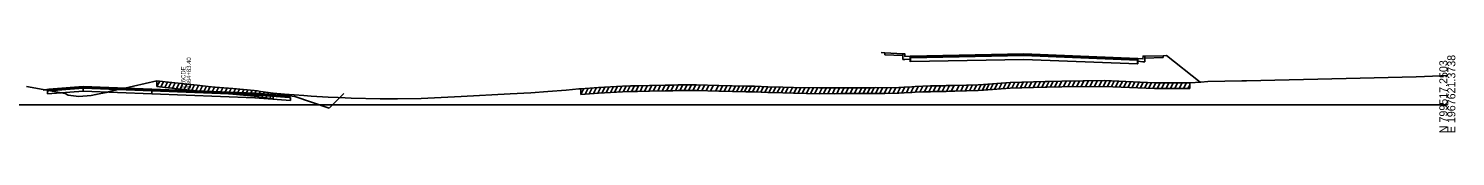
# Model space of a CAD drawing. Extents: x 1017 to 19997, y -1947 to 50737.
# Drawn here: x 14703.7 to 15202.8, y 14490.3 to 14518.2 of the extents above; entities that cross this region are included whole.
import ezdxf

# ---------------------------------------------------------------- set-up
doc = ezdxf.new("R2010")
doc.units = 0
for name, color, linetype in [('RD_GPK_XS_Cell', 7, 'Continuous'), ('RD_XS_Base', 7, 'Continuous'), ('RD_XS_CurbBase', 7, 'Continuous'), ('RD_XS_ExGround', 7, 'Continuous'), ('RD_XS_ExPaveRet', 7, 'Continuous'), ('RD_XS_Greenside', 7, 'Continuous'), ('RD_XS_Pave', 7, 'Continuous'), ('RD_XS_PaveOvlay', 7, 'Continuous'), ('RD_XS_SW', 7, 'Continuous'), ('RD_XS_SWbase', 7, 'Continuous'), ('RD_XS_TieSlope', 7, 'Continuous'), ('RD_XS_TX_Notes', 7, 'Continuous')]:
    doc.layers.add(name, color=color, linetype=linetype)

msp = doc.modelspace()

# ---------------------------------------------------------------- linework, layer by layer
at = {"layer": 'RD_GPK_XS_Cell'}
msp.add_line((14600, 14500), (15200, 14500), dxfattribs=at)
at = {"layer": 'RD_XS_Base'}
for points in [[(15012.08, 14515.09), (15012.08, 14516.43)], [(15012.21, 14515.1), (15012.08, 14515.09)], [(15012.21, 14515.1), (15012.21, 14516.43)], [(15091.58, 14514.29), (15051.89, 14515.9), (15012.21, 14515.1)], [(15091.58, 14515.62), (15091.58, 14514.29)], [(15091.7, 14515.62), (15091.7, 14514.28)], [(15091.7, 14514.28), (15091.58, 14514.29)], [(14710.32, 14504.78), (14710.82, 14504.82), (14722.82, 14505.79)], [(14722.82, 14504.79), (14710.32, 14503.78)], [(14710.32, 14503.78), (14710.32, 14504.78)], [(14722.82, 14504.79), (14722.82, 14505.79)], [(14782.83, 14502.46), (14758.82, 14503.39), (14722.82, 14504.79)], [(14746.82, 14504.86), (14746.82, 14503.86)], [(14782.83, 14502.46), (14758.82, 14503.39), (14746.82, 14503.86)], [(14782.83, 14503.46), (14782.83, 14502.46)], [(14782.83, 14503.46), (14794.83, 14502.51), (14795.33, 14502.47)], [(14795.33, 14501.47), (14782.83, 14502.46)], [(14795.33, 14502.47), (14795.33, 14501.47)]]:
    msp.add_lwpolyline(points, dxfattribs=at)
at = {"layer": 'RD_XS_CurbBase'}
for points in [[(15012.08, 14517.02), (15010.29, 14516.88), (15010.18, 14517.88), (15009.55, 14517.89)], [(15009.55, 14517.89), (15009.55, 14515.89)], [(15009.55, 14515.89), (15010.29, 14515.88), (15012.08, 14516.02)], [(15012.08, 14516.02), (15012.08, 14517.02)], [(15091.7, 14516.21), (15093.5, 14516.03), (15093.6, 14517.03), (15094.23, 14517.02)], [(15091.7, 14515.21), (15091.7, 14516.21)], [(15094.23, 14515.02), (15093.5, 14515.03), (15091.7, 14515.21)], [(15094.23, 14517.02), (15094.23, 14515.02)]]:
    msp.add_lwpolyline(points, dxfattribs=at)
at = {"layer": 'RD_XS_ExGround'}
msp.add_lwpolyline([(14702.99, 14506.37), (14716.51, 14503.89), (14717.58, 14503.31), (14721.28, 14502.85), (14725.61, 14503.19), (14727.28, 14503.52), (14730.93, 14504.25), (14733.02, 14504.83), (14736.32, 14505.58), (14748.65, 14508.33), (14751.54, 14508.01), (14757.26, 14507.44), (14759.06, 14507.25), (14762.67, 14506.84), (14766.55, 14506.41), (14769, 14506.15), (14775.14, 14505.66), (14782.63, 14504.99), (14783.78, 14504.82), (14784.9, 14504.64), (14789.27, 14504.03), (14791.96, 14503.77), (14793.25, 14503.68), (14799.96, 14503.17), (14802.54, 14503), (14808.56, 14502.68), (14812.03, 14502.48), (14814.53, 14502.36), (14816.53, 14502.28), (14826.74, 14502.05), (14827.29, 14502.04), (14828.39, 14502.01), (14832.79, 14502.1), (14841.06, 14502.14), (14855.03, 14502.88), (14872.19, 14503.85), (14879.41, 14504.11), (14885.37, 14504.63), (14891.81, 14505.08), (14896.21, 14505.51), (14896.9, 14505.57), (14903.03, 14506.09), (14911.54, 14506.51), (14914.28, 14506.58), (14916.75, 14506.65), (14920.96, 14506.73), (14926.42, 14506.84), (14929.03, 14506.89), (14930.94, 14506.95), (14936.11, 14506.95), (14936.93, 14506.95), (14937.41, 14506.96), (14945.2, 14506.77), (14954.6, 14506.54), (14957.66, 14506.47), (14962.29, 14506.31), (14967.62, 14506.17), (14971.27, 14506.07), (14980.41, 14505.86), (14981.09, 14505.88), (14985.75, 14505.86), (14988.27, 14505.87), (14988.91, 14505.87), (14990.77, 14505.89), (14993.05, 14505.9), (14998.86, 14505.94), (14999.91, 14505.98), (15003.19, 14505.94), (15008.16, 14506.08), (15009.95, 14506.14), (15012.73, 14506.31), (15013.84, 14506.36), (15016.53, 14506.49), (15019.24, 14506.57), (15020.34, 14506.61), (15023.13, 14506.65), (15024.15, 14506.67), (15024.64, 14506.68), (15025.78, 14506.71), (15026.81, 14506.73), (15027.68, 14506.74), (15035.9, 14506.97), (15037.7, 14507.09), (15047.11, 14507.81), (15059.38, 14508.13), (15059.96, 14508.18), (15065.13, 14508.29), (15080.09, 14508.43), (15097.55, 14507.71), (15109.88, 14507.63), (15113.72, 14507.86), (15116.17, 14508.08), (15128.17, 14508.4), (15128.72, 14508.41), (15129.69, 14508.41), (15164.57, 14509.15), (15189.07, 14509.81), (15197.69, 14510.13), (15200, 14510.19)], dxfattribs=at)
at = {"layer": 'RD_XS_ExPaveRet'}
for p, q in [((14748.65, 14506.33), (14748.65, 14508.33)), ((14748.65, 14506.33), (14749.6, 14508.23)), ((14750, 14506.18), (14750.95, 14508.08)), ((14751.35, 14506.04), (14752.3, 14507.94)), ((14752.71, 14505.9), (14753.66, 14507.8)), ((14754.06, 14505.76), (14755.02, 14507.66)), ((14755.42, 14505.62), (14756.37, 14507.53)), ((14756.78, 14505.48), (14757.73, 14507.39)), ((14758.15, 14505.35), (14759.11, 14507.25)), ((14759.52, 14505.2), (14760.47, 14507.09)), ((14760.89, 14505.04), (14761.83, 14506.94)), ((14762.25, 14504.89), (14763.2, 14506.78)), ((14763.62, 14504.73), (14764.56, 14506.63)), ((14764.98, 14504.58), (14765.93, 14506.48)), ((14766.35, 14504.43), (14767.3, 14506.33)), ((14767.79, 14504.28), (14768.74, 14506.17)), ((14769.25, 14504.13), (14770.21, 14506.05)), ((14770.72, 14504.01), (14771.68, 14505.93)), ((14772.19, 14503.89), (14773.15, 14505.82)), ((14773.66, 14503.78), (14774.62, 14505.7)), ((14775.13, 14503.66), (14776.08, 14505.58)), ((14776.59, 14503.53), (14777.55, 14505.45)), ((14778.05, 14503.4), (14779.01, 14505.31)), ((14779.52, 14503.27), (14780.47, 14505.18)), ((14780.98, 14503.14), (14781.94, 14505.05)), ((14782.44, 14503.01), (14783.38, 14504.88)), ((14783.87, 14502.81), (14784.79, 14504.66)), ((14785.29, 14502.59), (14786.22, 14504.46)), ((14896.9, 14503.57), (14897.95, 14505.66)), ((14896.9, 14503.57), (14896.9, 14505.57)), ((14898.39, 14503.69), (14899.43, 14505.78)), ((14899.88, 14503.82), (14900.92, 14505.91)), ((14901.37, 14503.95), (14902.41, 14506.03)), ((14902.86, 14504.07), (14903.88, 14506.13)), ((14904.32, 14504.15), (14905.34, 14506.2)), ((14905.79, 14504.22), (14906.81, 14506.28)), ((14907.27, 14504.3), (14908.29, 14506.35)), ((14908.74, 14504.37), (14909.77, 14506.42)), ((14910.22, 14504.45), (14911.25, 14506.5)), ((14911.7, 14504.52), (14912.71, 14506.54)), ((14913.16, 14504.55), (14914.17, 14506.58)), ((14914.62, 14504.59), (14915.64, 14506.62)), ((14916.09, 14504.63), (14917.1, 14506.66)), ((14917.62, 14504.67), (14918.63, 14506.68)), ((14919.16, 14504.69), (14920.17, 14506.71)), ((14920.71, 14504.72), (14921.72, 14506.74)), ((14922.25, 14504.76), (14923.26, 14506.78)), ((14923.8, 14504.79), (14924.81, 14506.81)), ((14925.34, 14504.82), (14926.35, 14506.84)), ((14926.88, 14504.85), (14927.89, 14506.87)), ((14928.43, 14504.88), (14929.44, 14506.9)), ((14929.98, 14504.92), (14931, 14506.95)), ((14931.53, 14504.95), (14932.53, 14506.95)), ((14933.07, 14504.95), (14934.07, 14506.95)), ((14934.6, 14504.95), (14935.6, 14506.95)), ((14936.14, 14504.95), (14937.14, 14506.95)), ((14937.67, 14504.95), (14938.66, 14506.93)), ((14939.19, 14504.91), (14940.18, 14506.89)), ((14940.71, 14504.88), (14941.69, 14506.85)), ((14942.29, 14504.84), (14943.27, 14506.82)), ((14944.03, 14504.8), (14945.02, 14506.77)), ((14945.56, 14504.76), (14946.54, 14506.74)), ((14947.08, 14504.72), (14948.07, 14506.7)), ((14948.55, 14504.69), (14949.54, 14506.66)), ((14950.02, 14504.65), (14951.01, 14506.63)), ((14951.46, 14504.62), (14952.45, 14506.59)), ((14952.88, 14504.58), (14953.87, 14506.56)), ((14954.13, 14504.55), (14955.12, 14506.53)), ((14955.52, 14504.52), (14956.51, 14506.5)), ((14956.97, 14504.48), (14957.95, 14506.46)), ((14958.4, 14504.44), (14959.39, 14506.41)), ((14959.84, 14504.39), (14960.82, 14506.36)), ((14961.28, 14504.35), (14962.26, 14506.31)), ((14962.71, 14504.3), (14963.7, 14506.27)), ((14964.15, 14504.26), (14965.14, 14506.23)), ((14965.59, 14504.22), (14966.58, 14506.2)), ((14967.03, 14504.18), (14968.01, 14506.16)), ((14968.49, 14504.14), (14969.48, 14506.12)), ((14969.96, 14504.11), (14970.94, 14506.08)), ((14971.42, 14504.07), (14972.41, 14506.05)), ((14972.89, 14504.04), (14973.88, 14506.01)), ((14974.36, 14504), (14975.34, 14505.98)), ((14975.82, 14503.97), (14976.81, 14505.94)), ((14977.29, 14503.93), (14978.28, 14505.91)), ((14978.76, 14503.9), (14979.74, 14505.87)), ((14980.27, 14503.86), (14981.29, 14505.88)), ((14981.82, 14503.88), (14982.82, 14505.87)), ((14983.36, 14503.87), (14984.36, 14505.87)), ((14984.89, 14503.86), (14985.89, 14505.86)), ((14986.43, 14503.86), (14987.43, 14505.87)), ((14987.97, 14503.87), (14988.98, 14505.88)), ((14989.52, 14503.88), (14990.52, 14505.89)), ((14991.06, 14503.89), (14992.06, 14505.9)), ((14992.61, 14503.9), (14993.62, 14505.9)), ((14994.17, 14503.91), (14995.18, 14505.92)), ((14995.62, 14503.92), (14996.63, 14505.93)), ((14997.07, 14503.93), (14998.07, 14505.94)), ((14998.52, 14503.94), (14999.53, 14505.96)), ((14999.98, 14503.98), (15000.97, 14505.96)), ((15001.49, 14503.96), (15002.48, 14505.95)), ((15003.01, 14503.94), (15004.02, 14505.96)), ((15004.55, 14503.98), (15005.57, 14506.01)), ((15006.1, 14504.02), (15007.12, 14506.05)), ((15007.66, 14504.07), (15008.67, 14506.1)), ((15009.21, 14504.12), (15010.23, 14506.16)), ((15010.78, 14504.19), (15011.81, 14506.26)), ((15012.35, 14504.29), (15013.38, 14506.34)), ((15013.93, 14504.37), (15014.95, 14506.41)), ((15015.5, 14504.44), (15016.52, 14506.49)), ((15017.07, 14504.5), (15018.08, 14506.53)), ((15018.63, 14504.55), (15019.64, 14506.58)), ((15020.19, 14504.6), (15021.2, 14506.62)), ((15021.74, 14504.63), (15022.74, 14506.65)), ((15023.28, 14504.66), (15024.29, 14506.68)), ((15024.83, 14504.68), (15025.84, 14506.71)), ((15026.45, 14504.72), (15027.46, 14506.74)), ((15028.24, 14504.76), (15029.25, 14506.79)), ((15029.8, 14504.8), (15030.81, 14506.83)), ((15031.36, 14504.85), (15032.38, 14506.88)), ((15032.88, 14504.89), (15033.89, 14506.92)), ((15034.38, 14504.93), (15035.4, 14506.96)), ((15035.86, 14504.97), (15036.89, 14507.04)), ((15037.35, 14505.06), (15038.38, 14507.14)), ((15038.65, 14505.16), (15039.69, 14507.24)), ((15040.12, 14505.27), (15041.16, 14507.35)), ((15041.64, 14505.39), (15042.68, 14507.47)), ((15043.16, 14505.5), (15044.19, 14507.58)), ((15044.67, 14505.62), (15045.71, 14507.7)), ((15046.19, 14505.74), (15047.23, 14507.81)), ((15047.69, 14505.82), (15048.71, 14507.85)), ((15049.17, 14505.86), (15050.18, 14507.89)), ((15050.65, 14505.9), (15051.66, 14507.93)), ((15052.13, 14505.94), (15053.14, 14507.97)), ((15053.63, 14505.98), (15054.64, 14508.01)), ((15055.13, 14506.02), (15056.15, 14508.04)), ((15056.64, 14506.06), (15057.65, 14508.08)), ((15058.14, 14506.1), (15059.15, 14508.12)), ((15059.65, 14506.15), (15060.68, 14508.2)), ((15061.16, 14506.21), (15062.18, 14508.23)), ((15062.66, 14506.24), (15063.68, 14508.26)), ((15064.16, 14506.27), (15065.17, 14508.29)), ((15065.71, 14506.3), (15066.72, 14508.31)), ((15067.26, 14506.31), (15068.26, 14508.32)), ((15068.81, 14506.33), (15069.81, 14508.34)), ((15070.35, 14506.34), (15071.36, 14508.35)), ((15071.9, 14506.36), (15072.9, 14508.37)), ((15073.44, 14506.37), (15074.45, 14508.38)), ((15074.99, 14506.39), (15076, 14508.39)), ((15076.54, 14506.4), (15077.54, 14508.41)), ((15078.09, 14506.41), (15079.1, 14508.42)), ((15079.66, 14506.43), (15080.65, 14508.41)), ((15081.1, 14506.39), (15082.08, 14508.35)), ((15082.52, 14506.33), (15083.5, 14508.29)), ((15083.95, 14506.27), (15084.93, 14508.23)), ((15085.38, 14506.21), (15086.36, 14508.17)), ((15086.83, 14506.15), (15087.81, 14508.11)), ((15088.29, 14506.09), (15089.27, 14508.05)), ((15089.74, 14506.03), (15090.72, 14507.99)), ((15091.2, 14505.97), (15092.18, 14507.93)), ((15092.65, 14505.91), (15093.63, 14507.87)), ((15094.1, 14505.85), (15095.08, 14507.81)), ((15095.56, 14505.79), (15096.54, 14507.75)), ((15097.01, 14505.73), (15098, 14507.7)), ((15098.53, 14505.7), (15099.53, 14507.69)), ((15100.07, 14505.69), (15101.06, 14507.69)), ((15101.6, 14505.68), (15102.6, 14507.68)), ((15103.14, 14505.67), (15104.13, 14507.67)), ((15104.67, 14505.66), (15105.67, 14507.66)), ((15106.2, 14505.65), (15107.2, 14507.65)), ((15107.74, 14505.64), (15108.73, 14507.64)), ((15109.27, 14505.64), (15109.88, 14506.85)), ((15109.88, 14505.63), (15109.88, 14507.63)), ((14786.72, 14502.39), (14787.65, 14504.26)), ((14788.15, 14502.19), (14789.08, 14504.06)), ((14789.27, 14502.03), (14789.27, 14504.03))]:
    msp.add_line(p, q, dxfattribs=at)
for points in [[(14748.65, 14506.33), (14751.54, 14506.01), (14757.26, 14505.44), (14759.06, 14505.25), (14762.67, 14504.84), (14766.55, 14504.41), (14769, 14504.15), (14775.14, 14503.66), (14782.63, 14502.99), (14783.78, 14502.82), (14784.9, 14502.64), (14789.27, 14502.03)], [(14896.9, 14503.57), (14903.03, 14504.09), (14911.54, 14504.51), (14914.28, 14504.58), (14916.75, 14504.65), (14920.96, 14504.73), (14926.42, 14504.84), (14929.03, 14504.89), (14930.94, 14504.95), (14936.11, 14504.95), (14936.93, 14504.95), (14937.41, 14504.96), (14945.2, 14504.77), (14954.6, 14504.54), (14957.66, 14504.47), (14962.29, 14504.31), (14967.62, 14504.17), (14971.27, 14504.07), (14980.41, 14503.86), (14981.09, 14503.88), (14985.75, 14503.86), (14988.27, 14503.87), (14988.91, 14503.87), (14990.77, 14503.89), (14993.05, 14503.9), (14998.86, 14503.94), (14999.91, 14503.98), (15003.19, 14503.94), (15008.16, 14504.08), (15009.95, 14504.14), (15012.73, 14504.31), (15013.84, 14504.36), (15016.53, 14504.49), (15019.24, 14504.57), (15020.34, 14504.61), (15023.13, 14504.65), (15024.15, 14504.67), (15024.64, 14504.68), (15025.78, 14504.71), (15026.81, 14504.73), (15027.68, 14504.74), (15035.9, 14504.97), (15037.7, 14505.09), (15047.11, 14505.81), (15059.38, 14506.13), (15059.96, 14506.18), (15065.13, 14506.29), (15080.09, 14506.43), (15097.55, 14505.71), (15109.88, 14505.63)]]:
    msp.add_lwpolyline(points, dxfattribs=at)
at = {"layer": 'RD_XS_Greenside'}
for points in [[(15003.23, 14518.19), (15001.97, 14518.25)], [(15100.55, 14517.17), (15101.82, 14517.2)], [(14710.82, 14505.45), (14708.82, 14505.13)], [(14794.83, 14503.15), (14796.83, 14502.83)], [(14796.83, 14502.83), (14808.83, 14498.84)]]:
    msp.add_lwpolyline(points, dxfattribs=at)
at = {"layer": 'RD_XS_Pave'}
for points in [[(15012.08, 14516.74), (15012.21, 14516.75)], [(15012.08, 14516.43), (15012.08, 14516.74)], [(15012.21, 14516.43), (15012.08, 14516.43)], [(15012.21, 14516.75), (15051.89, 14517.55), (15091.58, 14515.94)], [(15091.58, 14515.62), (15051.89, 14517.23), (15012.21, 14516.43)], [(15012.21, 14516.43), (15012.21, 14516.75)], [(15091.58, 14515.94), (15091.58, 14515.62)], [(15091.58, 14515.94), (15091.7, 14515.93)], [(15091.7, 14515.62), (15091.58, 14515.62)], [(15091.7, 14515.93), (15091.7, 14515.62)], [(14710.82, 14505.14), (14722.82, 14506.11)], [(14722.82, 14505.79), (14710.82, 14504.82)], [(14710.82, 14504.82), (14710.82, 14505.14)], [(14782.83, 14503.78), (14758.82, 14504.71), (14722.82, 14506.11)], [(14722.82, 14506.11), (14722.82, 14505.79)], [(14722.82, 14505.79), (14758.82, 14504.39), (14782.83, 14503.46)], [(14782.83, 14503.78), (14758.82, 14504.71), (14746.82, 14505.18)], [(14746.82, 14505.18), (14746.82, 14504.86)], [(14746.82, 14504.86), (14758.82, 14504.39), (14782.83, 14503.46)], [(14782.83, 14503.46), (14782.83, 14503.78)], [(14782.83, 14503.78), (14794.83, 14502.83)], [(14794.83, 14502.51), (14782.83, 14503.46)], [(14794.83, 14502.83), (14794.83, 14502.51)]]:
    msp.add_lwpolyline(points, dxfattribs=at)
at = {"layer": 'RD_XS_PaveOvlay'}
for points in [[(15012.08, 14516.74), (15012.08, 14517.02), (15012.08, 14517.06)], [(15012.08, 14517.06), (15012.21, 14517.06)], [(15012.08, 14517.06), (15012.21, 14517.06)], [(15012.21, 14517.06), (15051.89, 14517.86), (15091.58, 14516.26)], [(15012.21, 14516.75), (15012.21, 14517.06)], [(15091.58, 14516.26), (15091.58, 14515.94)], [(15091.58, 14516.26), (15091.7, 14516.25)], [(15091.7, 14516.25), (15091.7, 14516.21), (15091.7, 14515.93)], [(14722.82, 14506.43), (14710.82, 14505.45)], [(14710.82, 14505.45), (14710.82, 14505.14)], [(14722.82, 14506.43), (14758.82, 14505.03), (14782.83, 14504.09)], [(14722.82, 14506.11), (14722.82, 14506.43)], [(14746.82, 14505.49), (14758.82, 14505.03), (14782.83, 14504.09)], [(14746.82, 14505.18), (14746.82, 14505.49)], [(14782.83, 14504.09), (14782.83, 14503.78)], [(14782.83, 14504.09), (14794.83, 14503.15)], [(14794.83, 14503.15), (14794.83, 14502.83)]]:
    msp.add_lwpolyline(points, dxfattribs=at)
at = {"layer": 'RD_XS_SW'}
for points in [[(15009.55, 14517.89), (15003.23, 14518.19)], [(15094.23, 14517.02), (15100.55, 14517.17)]]:
    msp.add_lwpolyline(points, dxfattribs=at)
at = {"layer": 'RD_XS_SWbase'}
for points in [[(15003.23, 14517.52), (15003.23, 14518.19)], [(15009.55, 14517.23), (15003.23, 14517.52)], [(15009.55, 14517.89), (15009.55, 14517.23)], [(15094.23, 14517.02), (15094.23, 14516.36)], [(15094.23, 14516.36), (15100.55, 14516.5)], [(15100.55, 14516.5), (15100.55, 14517.17)]]:
    msp.add_lwpolyline(points, dxfattribs=at)
at = {"layer": 'RD_XS_TieSlope'}
for points in [[(15101.82, 14517.2), (15113.51, 14507.89)], [(14808.83, 14498.84), (14813.96, 14503.98)]]:
    msp.add_lwpolyline(points, dxfattribs=at)

# ---------------------------------------------------------------- texts
at = {"layer": 'RD_GPK_XS_Cell'}
for s, p in [('N 799517.2503', (15200, 14490)), ('E 1967621.3738', (15202.8, 14490))]:
    msp.add_text(s, height=2.8, rotation=90, dxfattribs=at).set_placement(p)
at = {"layer": 'RD_XS_TX_Notes'}
for s, p in [(' 8364+83.40', (14760.55, 14505.03)), (' 126CDE', (14758.6, 14505.03))]:
    msp.add_text(s, height=1.5, rotation=90, dxfattribs=at).set_placement(p)

doc.saveas('drawing.dxf')
